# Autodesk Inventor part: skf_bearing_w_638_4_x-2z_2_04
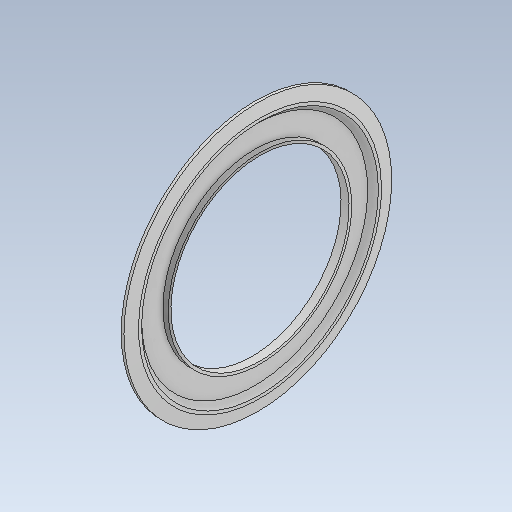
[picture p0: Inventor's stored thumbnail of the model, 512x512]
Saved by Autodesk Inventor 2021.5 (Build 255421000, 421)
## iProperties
Created: 2023-12
Part Number: skf_bearing_w_638_4_x-2z_2_04
Checked By: TraceParts S.A.
Material: Generic
Catalog Web Link: www.traceparts.com
Document SubType Name: Modeling
Designer: TraceParts
Density: 1 g/cm^3
Appearance: Default
Company: TraceParts S.A.
Author: TraceParts
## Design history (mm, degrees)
feature "skf_bearing_w_638_4_x-2z_2_04.ipt"
body "Solid1"
